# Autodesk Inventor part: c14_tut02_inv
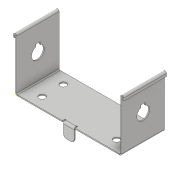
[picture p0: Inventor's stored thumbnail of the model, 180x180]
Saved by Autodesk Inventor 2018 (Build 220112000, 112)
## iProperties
Created: 2015-06
Part Number: c14_tut02_inv
Material: Generic
Document SubType Name: Sheet Metal
Designer: Sandeep
Density: 1 g/cm^3
Sheet Metal Rule: Default_mm
Appearance: Default
Flat Pattern Width: 5.12619 cm
Flat Pattern Length: 20.443 cm
Flat Pattern Area: 104.795 cm^2
Sheet Metal Width: 51.262 mm
Sheet Metal Length: 204.430 mm
Sheet Metal Area: 10479.484 mm^2
Author: Sandeep
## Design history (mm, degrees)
sketch "Sketch1"
  geometry: 1 further point
node "Face1"
  sketch "Sketch2"
    geometry: L1 (0, 0)-(100, 0); L2 (100, 0)-(100, 40); L3 (100, 40)-(0, 40); L4 (0, 40)-(0, 0)
    constraints: 8 end point, 2 parallel, 1 horizontal, 1 perpendicular
    dimensions: "d0" = 100 distance between parallel lines of L2 L4; "d1" = 40 distance between parallel lines of L1 L3
hole "Hole1" diameter "d5" = 6; stored, may be unused: countersink angle "d9" = 90 deg, drill point angle "d11" = 118 deg; dims "d3" = 10, "d4" = 15, "d6" = 6, "d7" = 4, "d8" = 2, "d10" = 1 (= Thickness)
pattern_linear "Rectangular Pattern1" dims "d14" = 20
pattern_linear "Rectangular Pattern2" dims "d17" = 70
node "Flange1"
node "Flange2"
feature "Hem1" dims "d38" = 1 (= BendReliefWidth), "d39" = 0.5 (= BendReliefDepth), "d40" = 2 (= MinimumRemnant), "d41" = 1 (= BendRadius), "d42" = 4 (= 4 x Thickness), "d43" = 1 (= Thickness), "d44" = 0.5 (= 0.5 x d43), "d82" = 1 (= Thickness), "SeamGap" = 0.01
feature "Hem2" dims "d45" = 1 (= BendReliefWidth), "d46" = 0.5 (= BendReliefDepth), "d47" = 2 (= MinimumRemnant), "d48" = 1 (= BendRadius), "d49" = 4 (= 4 x Thickness), "d50" = 1 (= Thickness), "d51" = 0.5 (= 0.5 x d50), "d82" = 1 (= Thickness), "SeamGap" = 0.01
sketch "Sketch7"
  geometry: L1 (0, 40)-(0, 0) reference; L2 (48, 0)-(0, 0) reference; 2 further points
  dimensions: "d52" = 25 distance from line of point (25, 20) L1; "d53" = 20 distance from line of L2 point (25, 20)
feature "iFeature15:1" sketch "Sketch7"
sketch "Sketch8"
  geometry: L1 (17.2, 18)-(17.2, 22) reference; L2 (19.343, 18)-(17.2, 18) reference; L3 (17.2, 22)-(19.343, 22) reference; L4 (17.2, 18)-(17.2, 22) reference; L5 (17.2, 22)-(19.343, 22) reference; L6 (19.343, 18)-(17.2, 18) reference; L7 (48, 0)-(48, 40) reference; L8 (48, 40)-(1.5, 40) reference; L9 (48, 0)-(1.5, 0) reference; L10 (1.5, 40)-(1.5, 0) reference; A1 r 6 centre (25, 20) between (19.343, 18) and (19.343, 22) reference; A2 r 6 centre (25, 20) between (19.343, 18) and (19.343, 22) reference; 1 further point
  node "Projected Loop1"
node "Flange3"
feature "Corner Round1" dims "d78" = 3
workplane "Work Plane1"
mirror "Mirror1"
body "Solid1"
face "Plate1" dims "d82" = 1 (= Thickness)
sketch "Sketch3"
  geometry: L1 through (20, 0) direction (-1, 0); L2 through (0, -25) direction (0, -1); L3 (0, -50)-(40, -50); L4 (40, -50)-(40, 0)
  constraints: 6 end point, 1 horizontal, 1 perpendicular, 1 vertical
face "Plate2" dims "d18" = 1 (= BendReliefWidth), "d19" = 0.5 (= BendReliefDepth), "d20" = 2 (= MinimumRemnant), "d21" = 1 (= BendRadius), "d22" = 50, "d23" = 90 deg, "d24" = 1 (= BendRadius), "d25" = 4 (= CornerReliefSize), "d26" = 1 (= GapSize), "d27" = 1 (= JacobiRadiusSize), "d82" = 1 (= Thickness), "SeamGap" = 0.01
bend "Bend1" dims "d18" = 1 (= BendReliefWidth), "d19" = 0.5 (= BendReliefDepth), "d20" = 2 (= MinimumRemnant), "d21" = 1 (= BendRadius), "d22" = 50, "d23" = 90 deg, "d24" = 1 (= BendRadius), "d82" = 1 (= Thickness), "SeamGap" = 0.01
feature "Corner1" dims "d22" = 50, "d23" = 90 deg, "d25" = 4 (= CornerReliefSize), "d26" = 1 (= GapSize), "d27" = 1 (= JacobiRadiusSize)
sketch "Sketch4"
  geometry: L1 through (20, 0) direction (-1, 5.47e-48); L2 through (0, -25) direction (-2.71e-32, -1); L3 (0, -50)-(40, -50); L4 (40, -50)-(40, 0)
  constraints: 6 end point, 1 horizontal, 1 perpendicular, 1 vertical
face "Plate3" dims "d28" = 1 (= BendReliefWidth), "d29" = 0.5 (= BendReliefDepth), "d30" = 2 (= MinimumRemnant), "d31" = 1 (= BendRadius), "d32" = 50, "d33" = 90 deg, "d34" = 1 (= BendRadius), "d35" = 4 (= CornerReliefSize), "d36" = 1 (= GapSize), "d37" = 1 (= JacobiRadiusSize), "d82" = 1 (= Thickness), "SeamGap" = 0.01
bend "Bend2" dims "d28" = 1 (= BendReliefWidth), "d29" = 0.5 (= BendReliefDepth), "d30" = 2 (= MinimumRemnant), "d31" = 1 (= BendRadius), "d32" = 50, "d33" = 90 deg, "d34" = 1 (= BendRadius), "d82" = 1 (= Thickness), "SeamGap" = 0.01
feature "Corner2" dims "d32" = 50, "d33" = 90 deg, "d35" = 4 (= CornerReliefSize), "d36" = 1 (= GapSize), "d37" = 1 (= JacobiRadiusSize)
sketch "Sketch9"
  geometry: L1 (-53, 0)-(-43, 0); L2 (-43, 0)-(-43, 13); L3 (-43, 13)-(-53, 13); L4 (-53, 13)-(-53, 0)
  constraints: 8 end point
face "Plate4" dims "d67" = 1 (= BendReliefWidth), "d68" = 0.5 (= BendReliefDepth), "d69" = 2 (= MinimumRemnant), "d70" = 1 (= BendRadius), "d71" = 10, "d72" = 13, "d73" = 90 deg, "d74" = 1 (= BendRadius), "d75" = 4 (= CornerReliefSize), "d76" = 1 (= GapSize), "d77" = 1 (= JacobiRadiusSize), "d82" = 1 (= Thickness), "SeamGap" = 0.01
bend "Bend3" dims "d67" = 1 (= BendReliefWidth), "d68" = 0.5 (= BendReliefDepth), "d69" = 2 (= MinimumRemnant), "d70" = 1 (= BendRadius), "d72" = 13, "d73" = 90 deg, "d74" = 1 (= BendRadius), "d82" = 1 (= Thickness), "SeamGap" = 0.01
feature "Corner3" dims "d72" = 13, "d73" = 90 deg, "d75" = 4 (= CornerReliefSize), "d76" = 1 (= GapSize), "d77" = 1 (= JacobiRadiusSize)
sketch "Sketch5"
  geometry: L1 (1, 0)-(0, 0); L2 (-1, 0)-(-1, -2.5); L3 (-1, -2.5)-(-2, -2.5); L4 (-2, -2.5)-(-2, 0); A1 r 0.5 centre (-0.5, 0) between (0, 0) and (-1, 0); A2 r 1.5 centre (-0.5, 0) between (1, 0) and (-2, 0); 2 further points
  constraints: 8 end point, 4 point on circle
sketch "Sketch6"
  geometry: L1 (0, 0)-(1, 0); L2 (2, 0)-(2, -2.5); L3 (2, -2.5)-(3, -2.5); L4 (3, -2.5)-(3, 0); A1 r 0.5 centre (1.5, 0) between (2, 0) and (1, 0); A2 r 1.5 centre (1.5, 0) between (3, 0) and (0, 0); 2 further points
  constraints: 8 end point, 4 point on circle
feature "Definition1"
other parameters: "Thickness" = 1 (derived), "BendRadius" = 1 (= Thickness), "BendReliefWidth" = 1 (= Thickness), "BendReliefDepth" = 0.5 (= 0.5 x Thickness), "CornerReliefSize" = 4 (= 4 x Thickness), "MinimumRemnant" = 2 (= 2 x Thickness), "TransitionRadius" = 1 (= BendRadius), "JacobiRadiusSize" = 1 (= BendRadius), "GapSize" = 1 (= Thickness), "d2" = 1 (= BendRadius), "d83" = 90 deg, "BendRadius" = 1, "BendReliefDepth" = 0.5, "BendReliefWidth" = 1, "CornerReliefSize" = 4, "GapSize" = 1, "JacobiRadiusSize" = 1, "MinimumRemnant" = 2, "Thickness" = 1, "TransitionRadius" = 1
